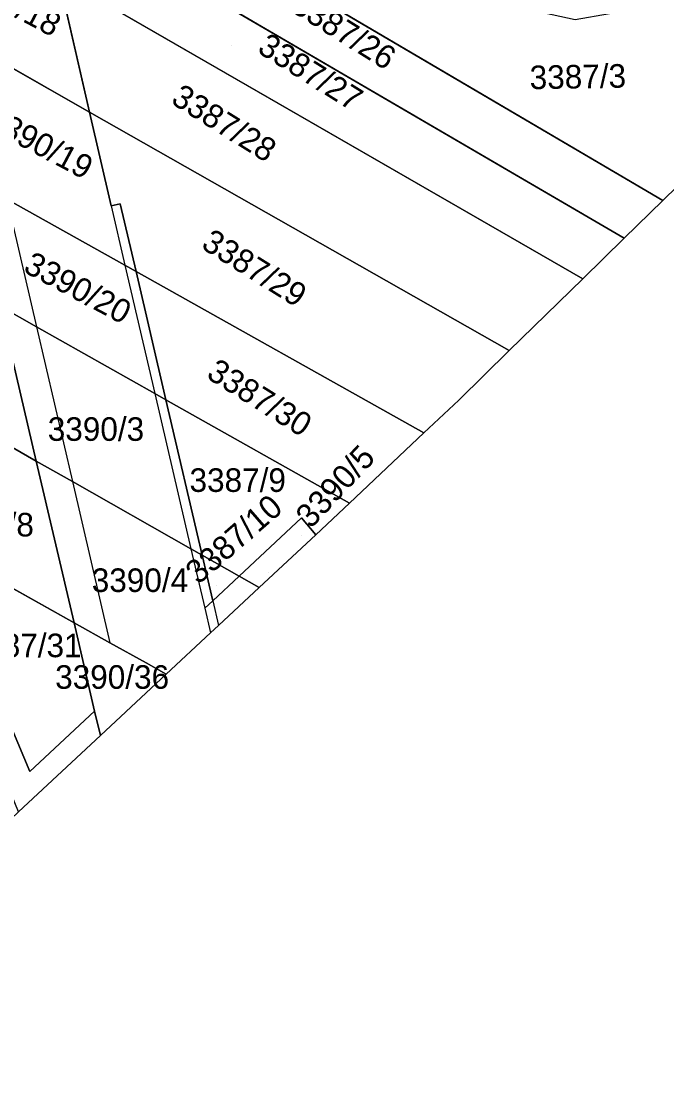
# Model space of a CAD drawing. Extents: x -262715 to -259381, y -1237238 to -1231182.
# Drawn here: x -261585.3 to -261530.6, y -1236858.1 to -1236768.1 of the extents above; entities that cross this region are included whole.
import ezdxf

# ---------------------------------------------------------------- set-up
doc = ezdxf.new("R2010")
doc.units = 0
for name, color, linetype in [('body_kn', 7, 'Continuous'), ('katuz_linie', 7, 'Continuous'), ('kladpar_druhypozemkov', 7, 'Continuous'), ('kladpar_hranice', 7, 'Continuous'), ('kladpar_parcelnecisla', 7, 'Continuous'), ('kladpar_plochy', 7, 'Continuous'), ('kladpar_sipky', 7, 'Continuous'), ('zappar_hrandruhpozemk', 7, 'Continuous'), ('zuob_linie', 7, 'Continuous'), ('zuob_plochy', 7, 'Continuous')]:
    doc.layers.add(name, color=color, linetype=linetype)

msp = doc.modelspace()

# ---------------------------------------------------------------- linework, layer by layer
at = {"layer": 'body_kn'}
for p, q in [((-261579.55, -1236775.76), (-261579.55, -1236775.76)), ((-261579.55, -1236775.76), (-261579.55, -1236775.76)), ((-261577.73, -1236783.72), (-261577.73, -1236783.72)), ((-261577.73, -1236783.72), (-261577.73, -1236783.72)), ((-261576.95, -1236783.55), (-261576.95, -1236783.55)), ((-261530.9, -1236783.26), (-261530.9, -1236783.26)), ((-261530.9, -1236783.26), (-261530.9, -1236783.26)), ((-261534.18, -1236786.46), (-261534.18, -1236786.46)), ((-261534.18, -1236786.46), (-261534.18, -1236786.46)), ((-261576.55, -1236788.76), (-261576.55, -1236788.76)), ((-261576.55, -1236788.76), (-261576.55, -1236788.76)), ((-261575.61, -1236789.29), (-261575.61, -1236789.29)), ((-261575.61, -1236789.29), (-261575.61, -1236789.29)), ((-261537.7, -1236789.9), (-261537.7, -1236789.9)), ((-261537.7, -1236789.9), (-261537.7, -1236789.9)), ((-261584.05, -1236793.97), (-261584.05, -1236793.97)), ((-261584.05, -1236793.97), (-261584.05, -1236793.97)), ((-261543.94, -1236796), (-261543.94, -1236796)), ((-261543.94, -1236796), (-261543.94, -1236796)), ((-261574.02, -1236799.63), (-261574.02, -1236799.63)), ((-261574.02, -1236799.63), (-261574.02, -1236799.63)), ((-261573.08, -1236800.16), (-261573.08, -1236800.16)), ((-261573.08, -1236800.16), (-261573.08, -1236800.16)), ((-261548.23, -1236800.2), (-261548.23, -1236800.2)), ((-261551.18, -1236802.98), (-261551.18, -1236802.98)), ((-261551.18, -1236802.98), (-261551.18, -1236802.98)), ((-261584.07, -1236805.36), (-261584.07, -1236805.36)), ((-261584.07, -1236805.36), (-261584.07, -1236805.36)), ((-261581, -1236807.09), (-261581, -1236807.09)), ((-261581, -1236807.09), (-261581, -1236807.09)), ((-261557.5, -1236808.93), (-261557.5, -1236808.93)), ((-261557.5, -1236808.93), (-261557.5, -1236808.93)), ((-261561.58, -1236810.18), (-261561.58, -1236810.18)), ((-261560.34, -1236811.61), (-261560.34, -1236811.61)), ((-261570.95, -1236812.8), (-261570.95, -1236812.8)), ((-261570.95, -1236812.8), (-261570.95, -1236812.8)), ((-261570, -1236813.34), (-261570, -1236813.34)), ((-261570, -1236813.34), (-261570, -1236813.34)), ((-261566.86, -1236815.12), (-261566.86, -1236815.12)), ((-261566.86, -1236815.12), (-261566.86, -1236815.12)), ((-261565.15, -1236816.09), (-261565.15, -1236816.09)), ((-261565.15, -1236816.09), (-261565.15, -1236816.09)), ((-261569.77, -1236817.84), (-261569.77, -1236817.84)), ((-261569.77, -1236817.84), (-261569.77, -1236817.84)), ((-261569.1, -1236817.21), (-261569.1, -1236817.21)), ((-261569.1, -1236817.21), (-261569.1, -1236817.21)), ((-261580.87, -1236819.08), (-261580.87, -1236819.08)), ((-261580.87, -1236819.08), (-261580.87, -1236819.08)), ((-261568.61, -1236819.31), (-261568.61, -1236819.31)), ((-261569.28, -1236819.94), (-261569.28, -1236819.94)), ((-261577.82, -1236820.78), (-261577.82, -1236820.78)), ((-261574.76, -1236822.49), (-261574.76, -1236822.49)), ((-261573.05, -1236823.45), (-261573.05, -1236823.45)), ((-261573.05, -1236823.45), (-261573.05, -1236823.45)), ((-261579.12, -1236826.57), (-261579.12, -1236826.57)), ((-261576.46, -1236826.63), (-261576.46, -1236826.63)), ((-261578.63, -1236828.65), (-261578.63, -1236828.65)), ((-261584.61, -1236831.7), (-261584.61, -1236831.7))]:
    msp.add_line(p, q, dxfattribs=at)
at = {"layer": 'katuz_linie'}
msp.add_lwpolyline([(-261519.57, -1236772.19), (-261530.9, -1236783.26), (-261534.18, -1236786.46), (-261537.7, -1236789.9), (-261543.94, -1236796), (-261548.23, -1236800.2), (-261551.18, -1236802.98), (-261557.5, -1236808.93), (-261560.34, -1236811.61), (-261565.15, -1236816.09), (-261568.61, -1236819.31), (-261569.28, -1236819.94), (-261573.05, -1236823.45), (-261576.46, -1236826.63), (-261578.63, -1236828.65), (-261585.57, -1236835.12), (-261597.07, -1236846.07), (-261601.99, -1236850.76), (-261606.96, -1236855.49), (-261612.43, -1236860.7)], dxfattribs=at)
at = {"layer": 'kladpar_druhypozemkov'}
for p, q in [((-261567.53, -1236770.09), (-261567.53, -1236770.09)), ((-261537.2, -1236771.87), (-261537.2, -1236771.87)), ((-261566.82, -1236776.8), (-261566.82, -1236776.8)), ((-261583.16, -1236777.75), (-261583.16, -1236777.75)), ((-261563.98, -1236788.66), (-261563.98, -1236788.66)), ((-261580.05, -1236789.92), (-261580.05, -1236789.92)), ((-261564.61, -1236798.69), (-261564.61, -1236798.69)), ((-261578.15, -1236801.39), (-261578.15, -1236801.39)), ((-261567.22, -1236806.65), (-261567.22, -1236806.65)), ((-261573.88, -1236814.91), (-261573.88, -1236814.91)), ((-261564.38, -1236814.8), (-261564.38, -1236814.8)), ((-261568.79, -1236815.9), (-261568.79, -1236815.9)), ((-261584.83, -1236820.14), (-261584.83, -1236820.14)), ((-261576.71, -1236823.17), (-261576.71, -1236823.17))]:
    msp.add_line(p, q, dxfattribs=at)
at = {"layer": 'kladpar_hranice'}
for p, q in [((-261530.9, -1236783.26), (-261585.13, -1236751.39)), ((-261585.13, -1236751.39), (-261530.9, -1236783.26)), ((-261534.18, -1236786.46), (-261583.73, -1236757.53)), ((-261583.73, -1236757.53), (-261534.18, -1236786.46)), ((-261582.18, -1236764.28), (-261579.55, -1236775.76)), ((-261537.7, -1236789.9), (-261582.18, -1236764.28)), ((-261582.18, -1236764.28), (-261537.7, -1236789.9)), ((-261579.55, -1236775.76), (-261582.18, -1236764.28)), ((-261579.55, -1236775.76), (-261589.66, -1236770.02)), ((-261589.66, -1236770.02), (-261579.55, -1236775.76)), ((-261543.94, -1236796), (-261579.55, -1236775.76)), ((-261579.55, -1236775.76), (-261543.94, -1236796)), ((-261530.9, -1236783.26), (-261534.18, -1236786.46)), ((-261534.18, -1236786.46), (-261537.7, -1236789.9)), ((-261575.61, -1236789.29), (-261573.08, -1236800.16)), ((-261551.18, -1236802.98), (-261575.61, -1236789.29)), ((-261575.61, -1236789.29), (-261551.18, -1236802.98)), ((-261573.08, -1236800.16), (-261575.61, -1236789.29)), ((-261537.7, -1236789.9), (-261543.94, -1236796)), ((-261584.07, -1236805.36), (-261587.13, -1236792.24)), ((-261587.13, -1236792.24), (-261584.07, -1236805.36)), ((-261584.07, -1236805.36), (-261599.33, -1236796.7)), ((-261599.33, -1236796.7), (-261584.07, -1236805.36)), ((-261573.08, -1236800.16), (-261570, -1236813.34)), ((-261573.08, -1236800.16), (-261557.5, -1236808.93)), ((-261570, -1236813.34), (-261573.08, -1236800.16)), ((-261557.5, -1236808.93), (-261573.08, -1236800.16)), ((-261551.18, -1236802.98), (-261557.5, -1236808.93)), ((-261584.07, -1236805.36), (-261580.87, -1236819.08)), ((-261580.87, -1236819.08), (-261584.07, -1236805.36)), ((-261580.87, -1236819.08), (-261592.7, -1236812.45)), ((-261592.7, -1236812.45), (-261580.87, -1236819.08)), ((-261566.86, -1236815.12), (-261570, -1236813.34)), ((-261570, -1236813.34), (-261566.86, -1236815.12)), ((-261565.15, -1236816.09), (-261566.86, -1236815.12)), ((-261566.86, -1236815.12), (-261565.15, -1236816.09))]:
    msp.add_line(p, q, dxfattribs=at)
for points in [[(-261518.23, -1236770.84), (-261519.57, -1236772.19), (-261530.9, -1236783.26)], [(-261579.55, -1236775.76), (-261577.73, -1236783.72), (-261576.95, -1236783.55), (-261575.61, -1236789.29)], [(-261575.61, -1236789.29), (-261576.95, -1236783.55), (-261577.73, -1236783.72), (-261579.55, -1236775.76)], [(-261575.61, -1236789.29), (-261576.55, -1236788.76), (-261586.58, -1236783.15)], [(-261586.58, -1236783.15), (-261576.55, -1236788.76), (-261575.61, -1236789.29)], [(-261587.13, -1236792.24), (-261584.05, -1236793.97), (-261574.02, -1236799.63), (-261573.08, -1236800.16)], [(-261573.08, -1236800.16), (-261574.02, -1236799.63), (-261584.05, -1236793.97), (-261587.13, -1236792.24)], [(-261543.94, -1236796), (-261548.23, -1236800.2), (-261551.18, -1236802.98)], [(-261570, -1236813.34), (-261570.95, -1236812.8), (-261581, -1236807.09), (-261584.07, -1236805.36)], [(-261584.07, -1236805.36), (-261581, -1236807.09), (-261570.95, -1236812.8), (-261570, -1236813.34)], [(-261557.5, -1236808.93), (-261560.34, -1236811.61), (-261561.58, -1236810.18), (-261566.86, -1236815.12)], [(-261566.86, -1236815.12), (-261561.58, -1236810.18), (-261560.34, -1236811.61), (-261565.15, -1236816.09)], [(-261592.7, -1236812.45), (-261584.61, -1236831.7), (-261579.12, -1236826.57), (-261578.63, -1236828.65), (-261585.57, -1236835.12), (-261593.99, -1236814.55), (-261595.6, -1236810.84)], [(-261580.87, -1236819.08), (-261579.12, -1236826.57), (-261584.61, -1236831.7), (-261592.7, -1236812.45)], [(-261570, -1236813.34), (-261569.1, -1236817.21), (-261566.86, -1236815.12)], [(-261566.86, -1236815.12), (-261569.1, -1236817.21), (-261570, -1236813.34)], [(-261565.15, -1236816.09), (-261568.61, -1236819.31), (-261569.28, -1236819.94), (-261573.05, -1236823.45)], [(-261573.05, -1236823.45), (-261574.76, -1236822.49), (-261577.82, -1236820.78), (-261580.87, -1236819.08)], [(-261580.87, -1236819.08), (-261577.82, -1236820.78), (-261574.76, -1236822.49), (-261573.05, -1236823.45)], [(-261573.05, -1236823.45), (-261576.46, -1236826.63), (-261578.63, -1236828.65), (-261579.12, -1236826.57), (-261580.87, -1236819.08)]]:
    msp.add_lwpolyline(points, dxfattribs=at)
at = {"layer": 'kladpar_plochy'}
for points in [[(-261526.69, -1236765.86), (-261518.23, -1236770.84), (-261519.57, -1236772.19), (-261530.9, -1236783.26), (-261585.13, -1236751.39), (-261590, -1236730.13), (-261585.18, -1236739.92), (-261580.74, -1236746.42), (-261571.43, -1236755.44), (-261558.51, -1236763.51), (-261538.34, -1236767.9)], [(-261585.13, -1236751.39), (-261530.9, -1236783.26), (-261534.18, -1236786.46), (-261583.73, -1236757.53)], [(-261583.73, -1236757.53), (-261534.18, -1236786.46), (-261537.7, -1236789.9), (-261582.18, -1236764.28)], [(-261592.4, -1236758.4), (-261582.18, -1236764.28), (-261579.55, -1236775.76), (-261589.66, -1236770.02)], [(-261582.18, -1236764.28), (-261537.7, -1236789.9), (-261543.94, -1236796), (-261579.55, -1236775.76)], [(-261589.66, -1236770.02), (-261579.55, -1236775.76), (-261577.73, -1236783.72), (-261576.95, -1236783.55), (-261575.61, -1236789.29), (-261576.55, -1236788.76), (-261586.58, -1236783.15)], [(-261579.55, -1236775.76), (-261543.94, -1236796), (-261548.23, -1236800.2), (-261551.18, -1236802.98), (-261575.61, -1236789.29), (-261576.95, -1236783.55), (-261577.73, -1236783.72)], [(-261605.58, -1236781.85), (-261587.13, -1236792.24), (-261584.07, -1236805.36), (-261599.33, -1236796.7)], [(-261586.58, -1236783.15), (-261576.55, -1236788.76), (-261575.61, -1236789.29), (-261573.08, -1236800.16), (-261574.02, -1236799.63), (-261584.05, -1236793.97), (-261587.13, -1236792.24), (-261588.56, -1236786.1), (-261586.04, -1236785.43)], [(-261575.61, -1236789.29), (-261551.18, -1236802.98), (-261557.5, -1236808.93), (-261573.08, -1236800.16)], [(-261587.13, -1236792.24), (-261584.05, -1236793.97), (-261574.02, -1236799.63), (-261573.08, -1236800.16), (-261570, -1236813.34), (-261570.95, -1236812.8), (-261581, -1236807.09), (-261584.07, -1236805.36)], [(-261599.33, -1236796.7), (-261584.07, -1236805.36), (-261580.87, -1236819.08), (-261592.7, -1236812.45)], [(-261573.08, -1236800.16), (-261557.5, -1236808.93), (-261560.34, -1236811.61), (-261561.58, -1236810.18), (-261566.86, -1236815.12), (-261570, -1236813.34)], [(-261584.07, -1236805.36), (-261581, -1236807.09), (-261570.95, -1236812.8), (-261570, -1236813.34), (-261569.1, -1236817.21), (-261566.86, -1236815.12), (-261565.15, -1236816.09), (-261568.61, -1236819.31), (-261569.28, -1236819.94), (-261573.05, -1236823.45), (-261574.76, -1236822.49), (-261577.82, -1236820.78), (-261580.87, -1236819.08)], [(-261566.86, -1236815.12), (-261561.58, -1236810.18), (-261560.34, -1236811.61), (-261565.15, -1236816.09)], [(-261595.6, -1236810.84), (-261592.7, -1236812.45), (-261584.61, -1236831.7), (-261579.12, -1236826.57), (-261578.63, -1236828.65), (-261585.57, -1236835.12), (-261593.99, -1236814.55)], [(-261592.7, -1236812.45), (-261580.87, -1236819.08), (-261579.12, -1236826.57), (-261584.61, -1236831.7)], [(-261570, -1236813.34), (-261566.86, -1236815.12), (-261569.1, -1236817.21)], [(-261580.87, -1236819.08), (-261577.82, -1236820.78), (-261574.76, -1236822.49), (-261573.05, -1236823.45), (-261576.46, -1236826.63), (-261578.63, -1236828.65), (-261579.12, -1236826.57)]]:
    msp.add_lwpolyline(points, close=True, dxfattribs=at)
at = {"layer": 'kladpar_sipky'}
msp.add_line((-261561.6, -1236811.71), (-261561.6, -1236811.71), dxfattribs=at)
at = {"layer": 'zappar_hrandruhpozemk'}
for p, q in [((-261577.73, -1236783.72), (-261576.55, -1236788.76)), ((-261586.04, -1236785.43), (-261584.05, -1236793.97)), ((-261576.55, -1236788.76), (-261574.02, -1236799.63)), ((-261584.05, -1236793.97), (-261581, -1236807.09)), ((-261574.02, -1236799.63), (-261570.95, -1236812.8)), ((-261581, -1236807.09), (-261577.82, -1236820.78)), ((-261569.77, -1236817.84), (-261569.28, -1236819.94)), ((-261569.1, -1236817.21), (-261568.61, -1236819.31))]:
    msp.add_line(p, q, dxfattribs=at)
msp.add_lwpolyline([(-261570.95, -1236812.8), (-261569.77, -1236817.84), (-261569.1, -1236817.21)], dxfattribs=at)
at = {"layer": 'zuob_linie'}
msp.add_lwpolyline([(-261519.57, -1236772.19), (-261530.9, -1236783.26), (-261534.18, -1236786.46), (-261537.7, -1236789.9), (-261543.94, -1236796), (-261548.23, -1236800.2), (-261551.18, -1236802.98), (-261557.5, -1236808.93), (-261560.34, -1236811.61), (-261565.15, -1236816.09), (-261568.61, -1236819.31), (-261569.28, -1236819.94), (-261573.05, -1236823.45), (-261576.46, -1236826.63), (-261578.63, -1236828.65), (-261585.57, -1236835.12), (-261597.07, -1236846.07), (-261601.99, -1236850.76), (-261606.96, -1236855.49), (-261612.43, -1236860.7)], dxfattribs=at)
at = {"layer": 'zuob_plochy'}
msp.add_lwpolyline([(-261519.57, -1236772.19), (-261530.9, -1236783.26), (-261534.18, -1236786.46), (-261537.7, -1236789.9), (-261543.94, -1236796), (-261548.23, -1236800.2), (-261551.18, -1236802.98), (-261557.5, -1236808.93), (-261560.34, -1236811.61), (-261565.15, -1236816.09), (-261568.61, -1236819.31), (-261569.28, -1236819.94), (-261573.05, -1236823.45), (-261576.46, -1236826.63), (-261578.63, -1236828.65), (-261585.57, -1236835.12), (-261597.07, -1236846.07), (-261601.99, -1236850.76), (-261606.96, -1236855.49), (-261612.43, -1236860.7)], dxfattribs=at)

# ---------------------------------------------------------------- texts
at = {"layer": 'kladpar_parcelnecisla'}
for s, rotation, p in [('3390/18', 332, (-261591.226, -1236764.896)), ('3387/26', 328, (-261562.594, -1236767.142)), ('3387/27', 328, (-261565.414, -1236770.647)), ('3387/3', 1, (-261542.193, -1236773.83)), ('3387/28', 328, (-261572.744, -1236774.97)), ('3390/19', 332, (-261588.515, -1236776.997)), ('3387/29', 328, (-261570.174, -1236787.262)), ('3390/20', 332, (-261585.271, -1236789.269)), ('3387/30', 328, (-261569.734, -1236798.257)), ('3390/5', 47, (-261560.775, -1236811.162)), ('3387/10', 41, (-261570.314, -1236815.895))]:
    msp.add_text(s, height=2, rotation=rotation, dxfattribs=at).set_placement(p)
for s, p in [('3390/3', (-261583.099, -1236803.65)), ('3387/9', (-261571.069, -1236807.98)), ('3387/8', (-261592.453, -1236811.76)), ('3390/4', (-261579.366, -1236816.47)), ('3387/31', (-261589.893, -1236822)), ('3390/36', (-261582.47, -1236824.68))]:
    msp.add_text(s, height=2, dxfattribs=at).set_placement(p)

doc.saveas('drawing.dxf')
